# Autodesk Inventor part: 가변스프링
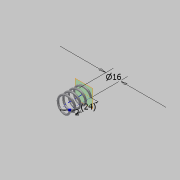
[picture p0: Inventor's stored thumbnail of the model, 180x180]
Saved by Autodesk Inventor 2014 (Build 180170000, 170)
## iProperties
Created: 2015-04
Part Number: 가변스프링
Material: 강철, 탄소
Document SubType Name: Modeling
Designer: Administrator
Mass: 4.7887 g
Surface Area: 12.5158 cm^2
Volume: 0.608475 cm^3
Density: 7.87 g/cm^3
Appearance: 반연마
Author: Administrator
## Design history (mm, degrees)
sketch "스케치1"
  geometry: L1 (0, 0)-(8, 0); L2 (8, 0)-(8, 11.5); L3 (8, 11.5)-(0, 11.5); L4 (0, 11.5)-(0, 0); C1 r 1 at (8, 0)
  constraints: 8 end point, 2 parallel, 1 centre point, 1 coincident, 1 horizontal, 1 perpendicular
  dimensions: "d0" = 16 diameter of L2 L4; "d1" = 11.50049 distance between parallel lines of L1 L3 (derived); "d2" = 2 diameter of C1
feature "코일1" pitch "d3" = 10; turns "d5" = 4; dims "d4" = 11.50049 (= d1), "d6" = 0, angle "d7" = 90 deg, angle "d8" = 90 deg, "d9" = 0, "d10" = 0
sketch "스케치2"
  geometry: L1 (-9, 0)-(-7, 0) reference; 1 further point
  constraints: 1 horizontal alignment
extrude "돌출1" cut sketch "스케치2" stored distance "d11" = 10; taper "d12" = 0 deg
node "작업 평면1"
sketch "스케치3"
  geometry: L1 (-7, 0)-(-9, 0) reference; 1 further point
  constraints: 1 horizontal alignment
extrude "돌출2" cut sketch "스케치3" stored distance "d13" = 10; taper "d14" = 0 deg
node "솔리드1"
node "절단 모서리 투영1"
node "절단 모서리 투영2"
